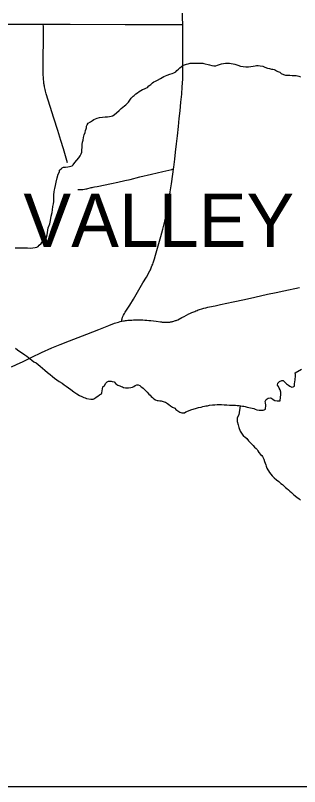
# Model space of a CAD drawing. Extents: x -59 to 82, y -3 to 49.
# Drawn here: x -9.656 to -9.154, y 28.548 to 29.913 of the extents above; entities that cross this region are included whole.
import ezdxf

# ---------------------------------------------------------------- set-up
doc = ezdxf.new("R2010")
doc.units = 0
for name, color, linetype in [('GM_X_City_Street', 7, 'Continuous'), ('GM_X_Corporation', 7, 'Continuous'), ('GM_X_Corporation_Text', 7, 'Continuous'), ('GM_X_County_Road', 7, 'Continuous'), ('GM_X_Minor_River', 7, 'Continuous'), ('SH_Data', 7, 'Continuous')]:
    doc.layers.add(name, color=color, linetype=linetype)

msp = doc.modelspace()

# ---------------------------------------------------------------- linework, layer by layer
at = {"layer": 'GM_X_City_Street'}
for points in [[(-9.6633, 29.2908), (-9.6545, 29.2948), (-9.6427, 29.3005), (-9.6275, 29.3079), (-9.6104, 29.3163), (-9.592, 29.3245), (-9.5775, 29.3303), (-9.5608, 29.3368), (-9.5453, 29.3428), (-9.53, 29.3487), (-9.5089, 29.3569), (-9.4915, 29.3638), (-9.481, 29.3679), (-9.4787, 29.3686), (-9.4763, 29.3693), (-9.474, 29.37), (-9.4713, 29.3708), (-9.4681, 29.3715), (-9.468, 29.3738), (-9.4678, 29.3755), (-9.4677, 29.3764), (-9.4676, 29.3772), (-9.4673, 29.3781), (-9.4671, 29.3789), (-9.4666, 29.3801), (-9.466, 29.3813), (-9.4656, 29.3821), (-9.4636, 29.3854), (-9.4624, 29.3874), (-9.4544, 29.4001), (-9.4477, 29.4106), (-9.4381, 29.4268), (-9.4309, 29.4395), (-9.4248, 29.4494), (-9.4188, 29.4605), (-9.4179, 29.4625), (-9.4169, 29.4644), (-9.4156, 29.4675), (-9.4144, 29.4705), (-9.4136, 29.4726), (-9.4129, 29.4747), (-9.4107, 29.4816), (-9.4086, 29.4886), (-9.404, 29.5047), (-9.3993, 29.5216), (-9.3959, 29.5341), (-9.3922, 29.5484), (-9.3886, 29.564), (-9.3827, 29.6006), (-9.3804, 29.6148), (-9.378, 29.6316), (-9.3768, 29.6405), (-9.3763, 29.644), (-9.3745, 29.6583), (-9.3734, 29.6707), (-9.3716, 29.6855), (-9.3701, 29.6996), (-9.3684, 29.7163), (-9.3669, 29.7303), (-9.3654, 29.7436), (-9.3639, 29.7588), (-9.3625, 29.7731), (-9.3616, 29.7863), (-9.3607, 29.7997), (-9.3603, 29.8146), (-9.3602, 29.8308), (-9.3603, 29.8804), (-9.3605, 29.8965)], [(-9.5643, 29.652), (-9.5657, 29.6561), (-9.5679, 29.6642), (-9.5716, 29.6766), (-9.5762, 29.691), (-9.5816, 29.7088), (-9.5883, 29.7306), (-9.5949, 29.7514), (-9.6018, 29.7739), (-9.6025, 29.7763), (-9.6031, 29.7788), (-9.6037, 29.7812), (-9.6043, 29.7837), (-9.6048, 29.7862), (-9.6051, 29.7876), (-9.6054, 29.7891), (-9.6057, 29.7905), (-9.606, 29.7919), (-9.6062, 29.7934), (-9.6063, 29.7948), (-9.6068, 29.7999), (-9.607, 29.8034), (-9.6073, 29.807), (-9.6074, 29.8106), (-9.6076, 29.8142), (-9.6075, 29.8259), (-9.6074, 29.8402), (-9.607, 29.8656), (-9.6066, 29.8772), (-9.6065, 29.8883), (-9.6066, 29.8905), (-9.6068, 29.8925), (-9.6074, 29.897)], [(-9.5459, 29.6048), (-9.5434, 29.6046), (-9.5373, 29.6048), (-9.5342, 29.6052), (-9.5322, 29.6056), (-9.5303, 29.606), (-9.5284, 29.6064), (-9.5245, 29.6074), (-9.5226, 29.6079), (-9.5207, 29.6083), (-9.5188, 29.6087), (-9.5168, 29.6091), (-9.5118, 29.61), (-9.4864, 29.6152), (-9.4754, 29.6176), (-9.4632, 29.6206), (-9.4535, 29.6225), (-9.4362, 29.6267), (-9.416, 29.6316), (-9.3959, 29.6366), (-9.3802, 29.6402), (-9.3794, 29.6403), (-9.3784, 29.6404), (-9.3768, 29.6405)], [(-9.4681, 29.3715), (-9.4655, 29.3721), (-9.4636, 29.3724), (-9.4617, 29.3726), (-9.4598, 29.3729), (-9.4578, 29.3731), (-9.4551, 29.3732), (-9.4523, 29.3734), (-9.4509, 29.3735), (-9.4476, 29.3737), (-9.4443, 29.3738), (-9.441, 29.3739), (-9.4311, 29.3738), (-9.4275, 29.3736), (-9.4239, 29.3733), (-9.4203, 29.373), (-9.4168, 29.3726), (-9.4076, 29.3714), (-9.4, 29.3704), (-9.3984, 29.3702), (-9.3968, 29.3701), (-9.3951, 29.3699), (-9.3934, 29.3698), (-9.3851, 29.3699), (-9.3836, 29.3701), (-9.3822, 29.3703), (-9.3807, 29.3706), (-9.3793, 29.3709), (-9.3779, 29.3712), (-9.3764, 29.3716), (-9.375, 29.372), (-9.3737, 29.3725), (-9.3723, 29.373), (-9.3709, 29.3735), (-9.3696, 29.3741), (-9.3622, 29.3778), (-9.3581, 29.3801), (-9.354, 29.3823), (-9.3499, 29.3844), (-9.3482, 29.3853), (-9.3448, 29.3868), (-9.3431, 29.3876), (-9.3413, 29.3883), (-9.3395, 29.389), (-9.3375, 29.3899), (-9.3354, 29.3907), (-9.3333, 29.3914), (-9.3311, 29.3922), (-9.3269, 29.3935), (-9.3235, 29.3944), (-9.32, 29.3953), (-9.3166, 29.3962), (-9.3131, 29.397), (-9.3034, 29.399), (-9.294, 29.401), (-9.2713, 29.4059), (-9.2513, 29.4101), (-9.2335, 29.4141), (-9.2109, 29.4191), (-9.1955, 29.4224), (-9.1819, 29.4254), (-9.1541, 29.4314)]]:
    msp.add_lwpolyline(points, dxfattribs=at)
at = {"layer": 'GM_X_Corporation'}
msp.add_lwpolyline([(-9.8377, 28.5482), (-8.3457, 28.5482), (-8.3427, 29.6972), (-8.3433, 29.7075), (-8.3984, 29.7816), (-8.4446, 29.8425), (-8.4738, 29.8757), (-8.4956, 29.9007), (-8.5146, 29.9208)], dxfattribs=at)
at = {"layer": 'GM_X_County_Road'}
for points in [[(-9.3605, 29.8965), (-9.3608, 29.9088), (-9.3609, 29.9166)], [(-9.6844, 29.8971), (-9.6236, 29.897), (-9.6074, 29.897), (-9.5596, 29.8968), (-9.4623, 29.8965), (-9.4199, 29.8964), (-9.3605, 29.8965)]]:
    msp.add_lwpolyline(points, dxfattribs=at)
at = {"layer": 'GM_X_Minor_River'}
for points in [[(-9.5386, 29.6789), (-9.5383, 29.6842), (-9.5376, 29.6884), (-9.5369, 29.6918), (-9.5362, 29.6964), (-9.5348, 29.7014), (-9.5333, 29.7052), (-9.5326, 29.7087), (-9.5315, 29.7117), (-9.5308, 29.7136), (-9.5305, 29.7167), (-9.5294, 29.719), (-9.5275, 29.7217), (-9.5237, 29.7244), (-9.5204, 29.7267), (-9.5177, 29.7283), (-9.5147, 29.7298), (-9.5117, 29.731), (-9.5075, 29.7319), (-9.5022, 29.7327), (-9.4976, 29.7331), (-9.4938, 29.7332), (-9.49, 29.7336), (-9.4874, 29.7341), (-9.4847, 29.7349), (-9.4821, 29.7364), (-9.4731, 29.7442), (-9.4697, 29.7476), (-9.4664, 29.7503), (-9.4633, 29.7523), (-9.4611, 29.7546), (-9.4589, 29.7569), (-9.4566, 29.7592), (-9.4544, 29.7627), (-9.4518, 29.7662), (-9.4484, 29.7696), (-9.4465, 29.7708), (-9.4435, 29.7739), (-9.4405, 29.7758), (-9.4379, 29.7778), (-9.4349, 29.7797), (-9.4315, 29.7813), (-9.4285, 29.7825), (-9.4258, 29.7837), (-9.4232, 29.7852), (-9.4206, 29.7879), (-9.4168, 29.7906), (-9.4142, 29.7933), (-9.4115, 29.7949), (-9.4085, 29.7961), (-9.4051, 29.798), (-9.3999, 29.8008), (-9.3942, 29.8043), (-9.3882, 29.807), (-9.3832, 29.8086), (-9.3795, 29.8098), (-9.3764, 29.811), (-9.3731, 29.813), (-9.3708, 29.8149), (-9.3682, 29.8172), (-9.3655, 29.8196), (-9.3629, 29.8219), (-9.3603, 29.8238), (-9.3573, 29.825), (-9.3542, 29.8262), (-9.3512, 29.827), (-9.3478, 29.8278), (-9.3444, 29.8282), (-9.3406, 29.8283), (-9.3353, 29.828), (-9.3315, 29.828), (-9.328, 29.8281), (-9.3254, 29.8278), (-9.3235, 29.8274), (-9.3135, 29.8249), (-9.3093, 29.8238), (-9.3055, 29.8235), (-9.3021, 29.8235), (-9.2995, 29.8243), (-9.2957, 29.8255), (-9.2919, 29.8267), (-9.2885, 29.8275), (-9.2851, 29.828), (-9.2813, 29.828), (-9.2778, 29.8281), (-9.2748, 29.8277), (-9.2717, 29.827), (-9.2687, 29.8263), (-9.2633, 29.8245), (-9.2587, 29.823), (-9.2538, 29.8223), (-9.2492, 29.8216), (-9.2446, 29.8217), (-9.2405, 29.8222), (-9.2363, 29.8226), (-9.2329, 29.8234), (-9.2302, 29.8238), (-9.2272, 29.8239), (-9.2241, 29.8235), (-9.2192, 29.8225), (-9.2153, 29.821)], [(-9.2153, 29.821), (-9.2111, 29.8195), (-9.2073, 29.8185), (-9.2039, 29.8177), (-9.2012, 29.8174), (-9.1989, 29.8167), (-9.197, 29.8156), (-9.1947, 29.8145), (-9.1924, 29.8133), (-9.1893, 29.8119), (-9.1866, 29.8096), (-9.1824, 29.8078), (-9.179, 29.8071), (-9.1756, 29.8067), (-9.1714, 29.8068), (-9.1672, 29.8065), (-9.1634, 29.8065), (-9.1603, 29.8062), (-9.1577, 29.8059), (-9.1557, 29.8051), (-9.1527, 29.804)], [(-9.657, 29.5014), (-9.6532, 29.5014), (-9.6491, 29.5015), (-9.6449, 29.5011), (-9.6399, 29.5012), (-9.635, 29.5013), (-9.63, 29.501), (-9.6255, 29.5014), (-9.6213, 29.5019), (-9.6186, 29.5023), (-9.616, 29.5039), (-9.6141, 29.5062), (-9.6111, 29.5093), (-9.6082, 29.5123), (-9.6048, 29.5151), (-9.6022, 29.5178), (-9.6004, 29.5246), (-9.5987, 29.5365), (-9.5957, 29.5437), (-9.5943, 29.5495), (-9.5929, 29.5571), (-9.5915, 29.5636), (-9.5908, 29.5685), (-9.5901, 29.5743), (-9.5891, 29.5792), (-9.5884, 29.5834), (-9.5885, 29.5891), (-9.5882, 29.5952), (-9.5879, 29.6002), (-9.5872, 29.604), (-9.5869, 29.6066), (-9.5858, 29.6116), (-9.5844, 29.6177), (-9.5826, 29.6253), (-9.5808, 29.6315), (-9.5786, 29.6357), (-9.5783, 29.6387), (-9.5756, 29.6414), (-9.5738, 29.643), (-9.5715, 29.6438), (-9.5677, 29.6442), (-9.5635, 29.6447), (-9.5605, 29.6455), (-9.5582, 29.6459), (-9.5559, 29.6467), (-9.5541, 29.6482), (-9.5511, 29.6521), (-9.5481, 29.6567), (-9.5444, 29.6605), (-9.5418, 29.6644), (-9.5399, 29.6678), (-9.5392, 29.6709), (-9.5389, 29.6747), (-9.5386, 29.6789)], [(-9.6564, 29.3237), (-9.6526, 29.3207), (-9.6483, 29.3177), (-9.6437, 29.3147), (-9.6399, 29.3121), (-9.6364, 29.3095), (-9.6333, 29.3073), (-9.6303, 29.305), (-9.6272, 29.3028), (-9.6241, 29.2998), (-9.6199, 29.2976), (-9.6164, 29.295), (-9.6129, 29.292), (-9.6087, 29.2886), (-9.6041, 29.2849), (-9.5994, 29.2807), (-9.5948, 29.277), (-9.5906, 29.274), (-9.5871, 29.271), (-9.5833, 29.2677), (-9.579, 29.2647), (-9.574, 29.2617), (-9.5702, 29.2591), (-9.5667, 29.2565), (-9.5625, 29.2535), (-9.5583, 29.2505), (-9.5532, 29.2464), (-9.5479, 29.2431), (-9.5429, 29.2401), (-9.539, 29.2383), (-9.5356, 29.2368), (-9.5329, 29.2357), (-9.531, 29.2349), (-9.523, 29.2335), (-9.5207, 29.2336), (-9.5188, 29.2336), (-9.5165, 29.2348), (-9.5135, 29.2371), (-9.5109, 29.239), (-9.5079, 29.2414), (-9.5045, 29.2429), (-9.5034, 29.2449), (-9.5017, 29.2552), (-9.499, 29.2579), (-9.4968, 29.2621), (-9.4942, 29.2644), (-9.4919, 29.2656), (-9.4893, 29.2656), (-9.487, 29.2653), (-9.4851, 29.2649), (-9.482, 29.2642), (-9.4786, 29.2608), (-9.4751, 29.2586), (-9.4716, 29.2571), (-9.4694, 29.256), (-9.4674, 29.2553), (-9.4651, 29.2542), (-9.4621, 29.2535), (-9.4568, 29.2535), (-9.4522, 29.254), (-9.4492, 29.2548), (-9.4469, 29.256), (-9.445, 29.2575), (-9.442, 29.2587), (-9.4397, 29.2591), (-9.4367, 29.2576), (-9.4347, 29.2561), (-9.4328, 29.2547), (-9.4305, 29.2532), (-9.4286, 29.2513), (-9.4263, 29.2487)], [(-9.1616, 29.275), (-9.1616, 29.2773), (-9.1621, 29.2799), (-9.1507, 29.2866)], [(-9.4263, 29.2487), (-9.4235, 29.2457), (-9.4208, 29.2427), (-9.4185, 29.2404), (-9.4162, 29.2385), (-9.4143, 29.2367), (-9.4116, 29.234), (-9.4085, 29.2326), (-9.4058, 29.2315), (-9.4039, 29.2311), (-9.4012, 29.2308), (-9.3986, 29.2304), (-9.3955, 29.2297), (-9.3936, 29.229), (-9.3913, 29.2283), (-9.3875, 29.226), (-9.3852, 29.2242), (-9.3821, 29.2219), (-9.3786, 29.2193), (-9.3748, 29.2175), (-9.3728, 29.2156), (-9.3709, 29.2141), (-9.3678, 29.2119), (-9.3659, 29.2107), (-9.364, 29.21), (-9.3621, 29.2093), (-9.3602, 29.2093), (-9.3575, 29.2097), (-9.3549, 29.2109), (-9.3443, 29.2156), (-9.3383, 29.2172), (-9.3326, 29.2188), (-9.328, 29.2197), (-9.325, 29.2205), (-9.3224, 29.2213), (-9.3201, 29.2217), (-9.3167, 29.2221), (-9.3133, 29.2229), (-9.3079, 29.2238), (-9.3041, 29.2238), (-9.3, 29.2243), (-9.2962, 29.2243), (-9.292, 29.224), (-9.2874, 29.2237), (-9.2828, 29.2234), (-9.2779, 29.2231), (-9.2722, 29.2228), (-9.2676, 29.2228), (-9.2646, 29.2225), (-9.2608, 29.2222), (-9.2581, 29.2218), (-9.255, 29.2215), (-9.2528, 29.2212), (-9.2501, 29.2204), (-9.2466, 29.2197), (-9.2436, 29.219), (-9.2409, 29.2183), (-9.2382, 29.2176), (-9.2352, 29.2168), (-9.2325, 29.2157), (-9.2295, 29.215), (-9.2253, 29.2143), (-9.2226, 29.214), (-9.2203, 29.214), (-9.2184, 29.2141), (-9.2165, 29.2148), (-9.2146, 29.216), (-9.214, 29.2229), (-9.2144, 29.227), (-9.2152, 29.2293), (-9.213, 29.2328), (-9.2096, 29.2351), (-9.2058, 29.2359), (-9.2035, 29.2352), (-9.2008, 29.2333), (-9.1978, 29.2315), (-9.1936, 29.2308), (-9.1917, 29.2304), (-9.1886, 29.2309), (-9.188, 29.2373), (-9.1873, 29.2411), (-9.1873, 29.243), (-9.1874, 29.2457), (-9.1886, 29.2503), (-9.1901, 29.2533), (-9.1913, 29.2563), (-9.1929, 29.2586), (-9.1926, 29.262), (-9.1896, 29.2647), (-9.1858, 29.2667), (-9.1831, 29.2667), (-9.1808, 29.2644), (-9.1773, 29.2607), (-9.1739, 29.2585), (-9.1712, 29.2566), (-9.1677, 29.2551), (-9.1655, 29.2555), (-9.1632, 29.2567), (-9.1629, 29.2605), (-9.1622, 29.2681), (-9.1616, 29.275)], [(-9.2594, 29.222), (-9.2616, 29.2058), (-9.2646, 29.2008), (-9.2645, 29.194), (-9.2629, 29.1879), (-9.2613, 29.1837), (-9.2589, 29.1769), (-9.2558, 29.1716), (-9.253, 29.1683), (-9.2511, 29.1668), (-9.2476, 29.1638), (-9.2442, 29.16), (-9.2395, 29.1551), (-9.2364, 29.1518), (-9.2341, 29.1484), (-9.231, 29.1461), (-9.2294, 29.1443), (-9.2279, 29.142), (-9.2259, 29.139), (-9.2232, 29.1356), (-9.2209, 29.1341), (-9.2197, 29.1322), (-9.2186, 29.13), (-9.2174, 29.1273), (-9.2162, 29.1235), (-9.215, 29.1201), (-9.2138, 29.1175), (-9.213, 29.1152), (-9.2118, 29.1118), (-9.2071, 29.1039), (-9.2052, 29.1012), (-9.2025, 29.0979), (-9.199, 29.0945), (-9.1951, 29.0911), (-9.1909, 29.0877), (-9.1874, 29.0844), (-9.1843, 29.0829), (-9.1828, 29.081), (-9.1808, 29.0791), (-9.1789, 29.0773), (-9.1766, 29.0754), (-9.1739, 29.0732), (-9.1716, 29.0709), (-9.1685, 29.0683), (-9.1642, 29.0642), (-9.1592, 29.0601), (-9.155, 29.0571), (-9.1523, 29.0552)]]:
    msp.add_lwpolyline(points, dxfattribs=at)
at = {"layer": 'SH_Data'}
msp.add_lwpolyline([(-15.0786, 28.5482), (-8.2786, 28.5482), (-8.2786, 35.3482), (-15.0786, 35.3482)], close=True, dxfattribs=at)

# ---------------------------------------------------------------- texts
at = {"layer": 'GM_X_Corporation_Text'}
msp.add_text('VALLEY VIEW', height=0.094697, rotation=0, dxfattribs=at).set_placement((-9.6423, 29.5027))

doc.saveas('drawing.dxf')
